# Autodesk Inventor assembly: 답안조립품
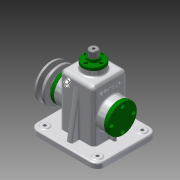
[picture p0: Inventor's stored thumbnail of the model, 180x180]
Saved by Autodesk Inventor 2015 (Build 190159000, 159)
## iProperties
Created: 2016-02
Part Number: 답안조립품
Document SubType Name: Assembly
Designer: Administrator
Author: Administrator
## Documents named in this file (15)
- C:\Users\Administrator\Desktop\460219V1001\답안조립품.iam
- C:\Users\Administrator\Desktop\460219V1001\V-벨트풀리.ipt
- C:\Users\Administrator\Desktop\460219V1001\고정핀.ipt
- C:\Users\Administrator\Desktop\460219V1001\뒤커버.ipt
- C:\Users\Administrator\Desktop\460219V1001\링크.ipt
- C:\Users\Administrator\Desktop\460219V1001\멈춤링 6 x 5.ipt
- C:\Users\Administrator\Desktop\460219V1001\멈춤링 15 x 1.ipt
- C:\Users\Administrator\Desktop\460219V1001\베어링 15 x 35 x 11.ipt
- C:\Users\Administrator\Desktop\460219V1001\본체.ipt
- C:\Users\Administrator\Desktop\460219V1001\상부부시.ipt
- C:\Users\Administrator\Desktop\460219V1001\슬라이드바.ipt
- C:\Users\Administrator\Desktop\460219V1001\앞커버.ipt
- C:\Users\Administrator\Desktop\460219V1001\오일실 15 25 7.ipt
- C:\Users\Administrator\Desktop\460219V1001\키 5 x 5 x 14.ipt
- C:\Users\Administrator\Desktop\460219V1001\편심축.ipt
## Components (2 placed, 2 different names)
1. V-벨트풀리:1
2. 고정핀:1
